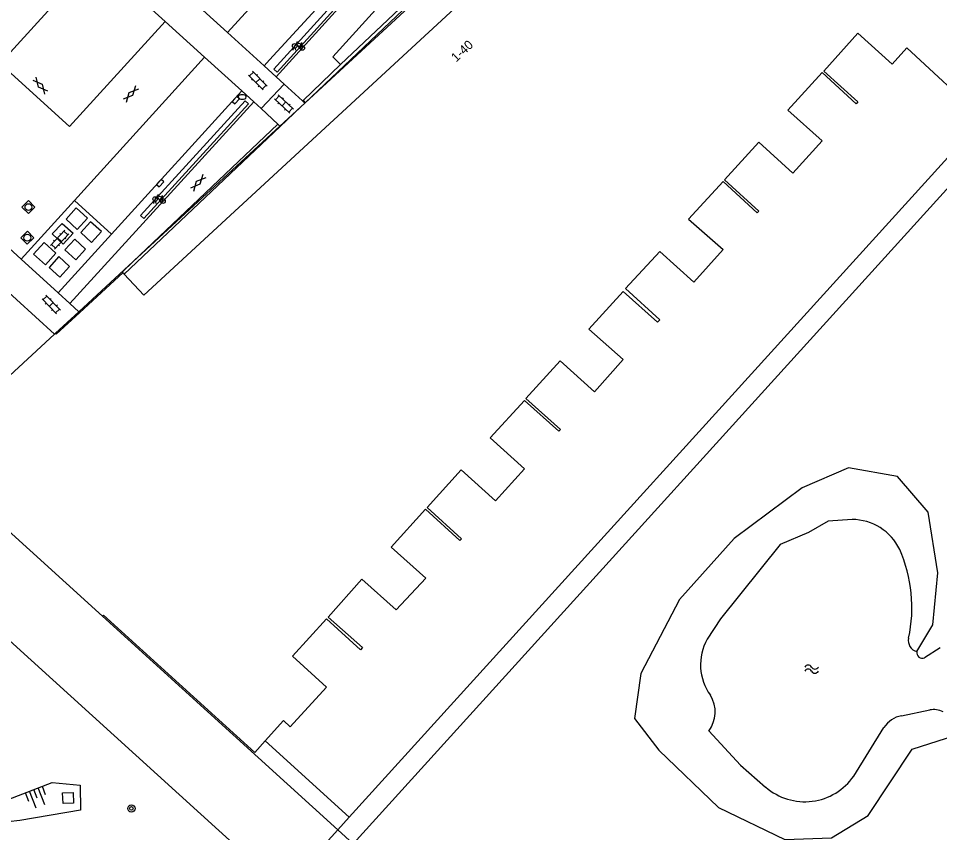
# Model space of a CAD drawing. Extents: x 124000 to 128010, y 398999 to 403000.
# Drawn here: x 127004.4 to 127105.7, y 399293.7 to 399383.3 of the extents above; entities that cross this region are included whole.
import ezdxf

# ---------------------------------------------------------------- set-up
doc = ezdxf.new("R2010")
doc.units = 0
for name, color, linetype in [('gg-afsc-hekwerk', 7, 'Continuous'), ('gg-afsc-muur', 7, 'Continuous'), ('gg-anno-huisnummerreeks BGT', 7, 'Continuous'), ('gg-bbg-hoofdgebouw', 7, 'Continuous'), ('gg-bbg-onder overbouw', 7, 'Continuous'), ('gg-bbg-pand overbouw', 7, 'Continuous'), ('gg-knt-BGT kruinlijn', 7, 'Continuous'), ('gg-knt-verharding', 7, 'Continuous'), ('gg-knt-verharding nz', 7, 'Continuous'), ('gg-kntw-bovenkant insteek waterloop', 7, 'Continuous'), ('gg-kntw-waterlijn', 7, 'Continuous'), ('gg-kwrk-afval apart plaats', 7, 'Continuous'), ('gg-kwrk-uitstroombak niveau min 01', 7, 'Continuous'), ('gt-grn-weggrens', 7, 'Continuous'), ('gt-symb-boom', 7, 'Continuous'), ('gt-symb-brandkraan', 7, 'Continuous'), ('gt-symb-fietsenrek', 7, 'Continuous'), ('gt-symb-gesloten verharding', 7, 'Continuous'), ('gt-symb-klinker verharding', 7, 'Continuous'), ('gt-symb-kolk', 7, 'Continuous'), ('gt-symb-rioolschacht', 7, 'Continuous'), ('gt-symb-talud symbool', 7, 'Continuous'), ('gt-symb-watersymbool', 7, 'Continuous')]:
    doc.layers.add(name, color=color, linetype=linetype)

# ---------------------------------------------------------------- blocks, each defined once
blk = doc.blocks.new('gt0-KL1')
at = {"layer": 'gt-symb-klinker verharding'}
for p, q in [((-1.15, 0.3), (1.15, 0.3)), ((-1, -0.3), (-1, 0.3)), ((-0.5, 0.3), (-0.5, 0.45)), ((0, -0.3), (0, 0.3)), ((0.5, 0.3), (0.5, 0.45)), ((1, -0.3), (1, 0.3)), ((-1.15, -0.3), (1.15, -0.3)), ((-0.5, -0.45), (-0.5, -0.3)), ((0.5, -0.45), (0.5, -0.3))]:
    blk.add_line(p, q, dxfattribs=at)
blk = doc.blocks.new('gt0-KOLK')
at = {"layer": 'gt-symb-kolk'}
blk.add_lwpolyline([(0, 0), (0.38, 0), (0.38, 0.4), (-0.38, 0.4), (-0.38, 0), (0, 0)], dxfattribs=at)
blk = doc.blocks.new('gt0-BR')
at = {"layer": 'gt-symb-brandkraan'}
for centre, radius, start, end in [((-0.24, 0), 0.206, 107.5669, 252.4331), ((0.6, -2.66), 3, 106.892, 107.5669), ((0, -0.69), 0.938, 73.108, 106.892), ((-0.6, -2.66), 3, 72.4331, 73.108), ((0.24, 0), 0.206, 287.567, 72.4331), ((0.6, 2.66), 3, 252.4331, 253.108), ((0, 0.69), 0.938, 253.108, 286.8921), ((-0.6, 2.66), 3, 286.8921, 287.567)]:
    blk.add_arc(centre, radius, start, end, dxfattribs=at)
blk = doc.blocks.new('gt0-GESVH1')
at = {"layer": 'gt-symb-gesloten verharding'}
for p, q in [((-0.99, -0.26), (0.01, 0.24)), ((0.01, -0.26), (-0.99, 0.24)), ((0.01, 0.24), (1.01, -0.26)), ((1.01, 0.24), (0.01, -0.26))]:
    blk.add_line(p, q, dxfattribs=at)
blk = doc.blocks.new('gt0-FREK')
at = {"layer": 'gt-symb-fietsenrek'}
for p, q in [((0.26, 0.76), (0.29, 0.82)), ((0.54, 0.34), (0.26, 0.76)), ((0.29, 0.82), (0.77, 0.71)), ((0.77, 0.71), (0.54, 0.34)), ((0.76, 0.84), (0.87, 0.82)), ((0.77, 0.71), (0.84, 0.82)), ((0.89, 0.25), (0.77, 0.71))]:
    blk.add_line(p, q, dxfattribs=at)
for points in [[(-0.12, 0), (-0.05, 0.31), (0.05, 0.31), (0.12, 0)], [(0.04, 0.48), (0.23, 0.71), (0.26, 0.76)], [(0.29, 0.82), (0.36, 0.94), (0.45, 0.93)], [(0.54, 0.34), (0.56, 0.31), (0.89, 0.25)]]:
    blk.add_lwpolyline(points, dxfattribs=at)
for centre in [(0.04, 0.48), (0.89, 0.25)]:
    blk.add_circle(centre, 0.252, dxfattribs=at)
blk = doc.blocks.new('gt0-RS')
at = {"layer": 'gt-symb-rioolschacht'}
blk.add_lwpolyline([(-0.5, -0.5), (0.5, -0.5), (0.5, 0.5), (-0.5, 0.5)], close=True, dxfattribs=at)
blk.add_circle((0, 0), 0.375, dxfattribs=at)
blk = doc.blocks.new('gt0-WA')
at = {"layer": 'gt-symb-watersymbool'}
for centre, start, end in [((-0.32, 0.02), 28.0725, 151.9275), ((0.43, 0.42), 208.0725, 331.9275), ((-0.32, -0.43), 28.0725, 151.9275), ((0.43, -0.03), 208.0725, 331.9275)]:
    blk.add_arc(centre, 0.425, start, end, dxfattribs=at)
blk = doc.blocks.new('gt0-BOOM')
at = {"layer": 'gt-symb-boom'}
for radius in [0.4, 0.2]:
    blk.add_circle((0, 0), radius, dxfattribs=at)
blk = doc.blocks.new('gt0-TALUD_1')
at = {"layer": 'gt-symb-talud symbool'}
for p, q in [((-1, -1), (-1, 0)), ((-0.5, -2), (-0.5, 0)), ((0, -1), (0, 0)), ((0.5, -2), (0.5, 0)), ((1, -1), (1, 0))]:
    blk.add_line(p, q, dxfattribs=at)

msp = doc.modelspace()

# ---------------------------------------------------------------- linework, layer by layer
at = {"layer": 'gg-afsc-hekwerk'}
msp.add_line((127040.77, 399295.43), (127031.53, 399303.83), dxfattribs=at)
at = {"layer": 'gg-afsc-muur'}
for p, q in [((127035.91, 399374), (127058.4, 399395.34)), ((127058.15, 399395.57), (127039.79, 399378.22)), ((127039.79, 399378.22), (127035.69, 399374.25)), ((127035.69, 399374.25), (127035.63, 399374.2)), ((127035.69, 399374.25), (127035.91, 399374)), ((126982.19, 399372.36), (127008.36, 399348.56)), ((127032.92, 399371.65), (127017.01, 399356.56)), ((127033.13, 399371.44), (127032.92, 399371.65)), ((127110.45, 399372.26), (127040.77, 399295.43)), ((127016.03, 399355.16), (127033.17, 399371.41)), ((127033.17, 399371.41), (127033.13, 399371.44)), ((127040.77, 399295.43), (127039.51, 399294.05))]:
    msp.add_line(p, q, dxfattribs=at)
for points in [[(127039.79, 399378.22), (127038.95, 399379.07), (127055.84, 399397.71)], [(127017.01, 399356.56), (127015.78, 399355.38), (127015.88, 399355.29)], [(126970.81, 399344.41), (127033.56, 399287.5), (127039.51, 399294.05)]]:
    msp.add_lwpolyline(points, dxfattribs=at)
at = {"layer": 'gg-bbg-hoofdgebouw'}
msp.add_line((127008.36, 399348.56), (127008.46, 399348.66), dxfattribs=at)
msp.add_lwpolyline([(127013.64, 399317.54), (126994.04, 399335.33), (127008.36, 399348.56)], dxfattribs=at)
at = {"layer": 'gg-bbg-onder overbouw'}
msp.add_line((127011.13, 399350.93), (127015.88, 399355.29), dxfattribs=at)
for points in [[(127016.03, 399355.16), (127018.17, 399352.83), (127080.84, 399410.71), (127089.85, 399402.52)], [(127110.45, 399372.26), (127102.08, 399380.05), (127100.45, 399378.25), (127096.68, 399381.65), (127092.93, 399377.49), (127096.67, 399374.09), (127096.49, 399373.9), (127092.76, 399377.34), (127088.99, 399373.2), (127092.75, 399369.83), (127089.55, 399366.26), (127085.8, 399369.67), (127082.02, 399365.53), (127085.81, 399362.09), (127085.63, 399361.9), (127081.87, 399365.34), (127078.08, 399361.2), (127081.86, 399357.85), (127078.67, 399354.26), (127074.9, 399357.66), (127071.15, 399353.57), (127074.93, 399350.14), (127074.67, 399349.86), (127070.9, 399353.26), (127067.12, 399349.12), (127070.9, 399345.76), (127067.74, 399342.21), (127063.96, 399345.61), (127060.19, 399341.48), (127063.99, 399338.07), (127063.81, 399337.88), (127060.04, 399341.28), (127056.27, 399337.14), (127060.02, 399333.76), (127056.83, 399330.23), (127053.06, 399333.63), (127049.32, 399329.49), (127053.09, 399326.06), (127052.92, 399325.88), (127049.14, 399329.3), (127045.39, 399325.15), (127049.17, 399321.74), (127045.93, 399318.23), (127042.14, 399321.6), (127038.45, 399317.45), (127042.23, 399314.09), (127042.02, 399313.86), (127038.27, 399317.26), (127034.53, 399313.14), (127038.28, 399309.74), (127034.27, 399305.39), (127033.55, 399306.07), (127031.53, 399303.83)], [(127015.88, 399355.29), (127015.9, 399355.31), (127016.03, 399355.16)], [(127008.46, 399348.66), (127008.55, 399348.55), (127011.13, 399350.93)], [(127013.64, 399317.54), (127013.74, 399317.65), (127030.38, 399302.56), (127031.53, 399303.83)]]:
    msp.add_lwpolyline(points, dxfattribs=at)
at = {"layer": 'gg-bbg-pand overbouw'}
for p, q in [((127035.43, 399373.56), (127033.13, 399371.44)), ((127035.87, 399373.97), (127035.43, 399373.56)), ((127035.91, 399374), (127035.87, 399373.97)), ((127033.13, 399371.44), (127017.01, 399356.56)), ((127017.01, 399356.56), (127011.03, 399351.03)), ((127011.03, 399351.03), (127008.46, 399348.66)), ((127013.64, 399317.54), (127039.51, 399294.05))]:
    msp.add_line(p, q, dxfattribs=at)
for points in [[(127035.91, 399374), (127079.55, 399414.3), (127091.17, 399403.74), (127089.85, 399402.52)], [(127112.1, 399370.72), (127041.19, 399292.52), (127039.51, 399294.05)]]:
    msp.add_lwpolyline(points, dxfattribs=at)
at = {"layer": 'gg-knt-BGT kruinlijn'}
msp.add_lwpolyline([(127002.56, 399297.11), (127003.28, 399297.38), (127008.09, 399299.25), (127011.18, 399298.95), (127011.2, 399296.2), (127004.53, 399295.07), (127000.66, 399294.65)], dxfattribs=at)
at = {"layer": 'gg-knt-verharding'}
for p, q in [((127032.74, 399376.86), (127053.57, 399399.87)), ((127020.51, 399382.95), (127012.88, 399389.88)), ((127027.37, 399381.73), (127023.03, 399385.68)), ((127024.86, 399379), (127020.51, 399382.95)), ((127031.41, 399378.05), (127027.37, 399381.73)), ((127028.94, 399375.3), (127024.86, 399379)), ((127032.01, 399378.71), (127031.41, 399378.05)), ((127033.61, 399376.06), (127032.74, 399376.86)), ((127031.08, 399373.38), (127033.61, 399376.06)), ((127033.61, 399376.06), (127035.63, 399374.2)), ((127014.62, 399359.55), (127028.94, 399375.3)), ((127010.05, 399351.93), (127030.26, 399374.1)), ((127030.26, 399374.1), (127031.08, 399373.38)), ((127035.43, 399373.56), (127033.17, 399371.41)), ((127035.63, 399374.2), (127035.87, 399373.97)), ((127032.92, 399371.65), (127031.08, 399373.38)), ((127004.7, 399356.79), (127010.56, 399363.25)), ((127010.56, 399363.25), (127014.62, 399359.55)), ((127000.31, 399360.77), (127004.7, 399356.79)), ((127008.76, 399353.1), (127014.62, 399359.55)), ((127004.7, 399356.79), (127008.76, 399353.1)), ((127011.03, 399351.03), (127010.05, 399351.93)), ((127011.13, 399350.93), (127011.03, 399351.03))]:
    msp.add_line(p, q, dxfattribs=at)
msp.add_lwpolyline([(127052.31, 399401.01), (127041.35, 399388.93), (127032.01, 399378.71)], dxfattribs=at)
at = {"layer": 'gg-knt-verharding nz'}
for p, q in [((127027.37, 399381.73), (127048.24, 399404.71)), ((127010.56, 399363.25), (127024.86, 399379))]:
    msp.add_line(p, q, dxfattribs=at)
for points in [[(127032.85, 399377.36), (127032.49, 399377.68), (127052.63, 399399.9), (127053, 399399.57), (127032.85, 399377.36)], [(127012.88, 399389.88), (127002.4, 399378.33), (127010.01, 399371.4), (127020.51, 399382.95)], [(127017.83, 399361.59), (127018.19, 399361.27), (127029.68, 399373.87), (127029.31, 399374.2), (127017.83, 399361.59)]]:
    msp.add_lwpolyline(points, dxfattribs=at)
at = {"layer": 'gg-kntw-bovenkant insteek waterloop'}
for points in [[(127103.17, 399313.65), (127104.93, 399316.58), (127105.48, 399322.3), (127104.4, 399328.98), (127101.05, 399332.92), (127095.64, 399333.84), (127090.57, 399331.65), (127083.08, 399326.07), (127077.09, 399319.39), (127072.81, 399311.24), (127072.13, 399306.28), (127074.8, 399302.8), (127081.35, 399296.51), (127088.67, 399292.99), (127093.8, 399293.18), (127097.81, 399295.62), (127102.65, 399302.92), (127107.36, 399304.44), (127116.14, 399303.25), (127119.98, 399302.18), (127120.17, 399301.3), (127119.31, 399300.54)], [(127105.74, 399314.06), (127104.01, 399312.98)]]:
    msp.add_lwpolyline(points, dxfattribs=at)
msp.add_arc((127103.77, 399313.53), 0.606, 169.2962, 293.9514, dxfattribs=at)
at = {"layer": 'gg-kntw-waterlijn'}
for p, q in [((127101.5, 399306.6), (127104.59, 399307.24)), ((127096.23, 399299.97), (127099.56, 399305.29))]:
    msp.add_line(p, q, dxfattribs=at)
for points in [[(127096.05, 399328.17), (127093.43, 399328.01), (127091.27, 399326.76), (127088.14, 399325.41), (127081.57, 399317.26), (127080.12, 399315.01)], [(127080.29, 399304.92), (127083.8, 399301.16), (127086.55, 399298.74)]]:
    msp.add_lwpolyline(points, dxfattribs=at)
for centre, radius, start, end in [((127096.02, 399322.31), 5.87, 26.1232, 89.6616), ((127086.88, 399318.52), 15.75, 347.5578, 23.8587), ((127085.19, 399312.21), 5.8, 151.1377, 215.4938), ((127103.5, 399314.87), 1.27, 168.2852, 255.055), ((127077.56, 399307.01), 3.44, 322.5438, 32.2312), ((127105.04, 399305.02), 2.26, 63.2054, 101.6461), ((127102.07, 399303.67), 2.99, 101.1421, 147.1222), ((127090.85, 399303.68), 6.54, 228.9774, 325.4299)]:
    msp.add_arc(centre, radius, start, end, dxfattribs=at)
at = {"layer": 'gg-kwrk-afval apart plaats'}
for points in [[(127009.63, 399361.22), (127010.86, 399360.07), (127012, 399361.31), (127010.75, 399362.45), (127009.63, 399361.22)], [(127008.11, 399359.58), (127009.21, 399360.71), (127010.4, 399359.66), (127009.3, 399358.46), (127008.11, 399359.58)], [(127013.51, 399359.84), (127012.32, 399360.91), (127011.25, 399359.73), (127012.43, 399358.65), (127013.51, 399359.84)], [(127007.21, 399358.63), (127008.51, 399357.48), (127007.37, 399356.18), (127006.06, 399357.35), (127007.21, 399358.63)], [(127011.77, 399357.92), (127010.58, 399359), (127009.51, 399357.82), (127010.69, 399356.74), (127011.77, 399357.92)], [(127010.02, 399356), (127008.84, 399357.08), (127007.76, 399355.9), (127008.95, 399354.82), (127010.02, 399356)]]:
    msp.add_lwpolyline(points, dxfattribs=at)
at = {"layer": 'gg-kwrk-uitstroombak niveau min 01'}
msp.add_lwpolyline([(127010.41, 399298.14), (127010.46, 399297), (127009.3, 399296.94), (127009.23, 399298.13), (127010.41, 399298.14)], dxfattribs=at)
at = {"layer": 'gt-grn-weggrens'}
for p, q in [((127031.41, 399378.05), (127032.74, 399376.86)), ((127028.94, 399375.3), (127030.26, 399374.1)), ((127008.76, 399353.1), (127010.05, 399351.93))]:
    msp.add_line(p, q, dxfattribs=at)

# ---------------------------------------------------------------- block references
at = {"layer": 'gt-symb-boom'}
msp.add_blockref('gt0-BOOM', (127016.81, 399296.4), dxfattribs=at)
at = {"layer": 'gt-symb-brandkraan'}
msp.add_blockref('gt0-BR', (127029, 399374.64), dxfattribs=at)
at = {"layer": 'gt-symb-fietsenrek'}
for p in [(127034.72, 399379.77), (127019.39, 399362.94)]:
    msp.add_blockref('gt0-FREK', p, dxfattribs=at)
at = {"layer": 'gt-symb-gesloten verharding'}
for p, rotation in [((127006.8, 399375.9), -49.46084825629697), ((127016.78, 399374.96), -132.24284336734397), ((127024.15, 399365.2), 47.75715663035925)]:
    msp.add_blockref('gt0-GESVH1', p, dxfattribs=dict(at, rotation=rotation))
at = {"layer": 'gt-symb-klinker verharding'}
for p, rotation in [((127030.71, 399376.44), -45.64829798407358), ((127033.58, 399373.87), 137.31004222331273), ((127008.92, 399358.96), 47.31004222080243), ((127008, 399351.82), -45.81035302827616)]:
    msp.add_blockref('gt0-KL1', p, dxfattribs=dict(at, rotation=rotation))
at = {"layer": 'gt-symb-kolk'}
for p, rotation in [((127028.15, 399374.42), -131.99999127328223), ((127019.84, 399365.29), -132.32381653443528)]:
    msp.add_blockref('gt0-KOLK', p, dxfattribs=dict(at, rotation=rotation))
at = {"layer": 'gt-symb-rioolschacht'}
for p, rotation in [((127005.49, 399362.53), 135.64829798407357), ((127005.37, 399359.16), 134.67584063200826)]:
    msp.add_blockref('gt0-RS', p, dxfattribs=dict(at, rotation=rotation))
at = {"layer": 'gt-symb-talud symbool', "xscale": 1.0005598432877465, "yscale": 1.000559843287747, "rotation": 21.333525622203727}
msp.add_blockref('gt0-TALUD_1', (127006.09, 399298.47), dxfattribs=at)
at = {"layer": 'gt-symb-watersymbool'}
msp.add_blockref('gt0-WA', (127091.54, 399311.73), dxfattribs=at)

# ---------------------------------------------------------------- texts
at = {"layer": 'gg-anno-huisnummerreeks BGT'}
msp.add_text('1-40', height=1, rotation=42.7, dxfattribs=at).set_placement((127052.52, 399378.43))

doc.saveas('drawing.dxf')
